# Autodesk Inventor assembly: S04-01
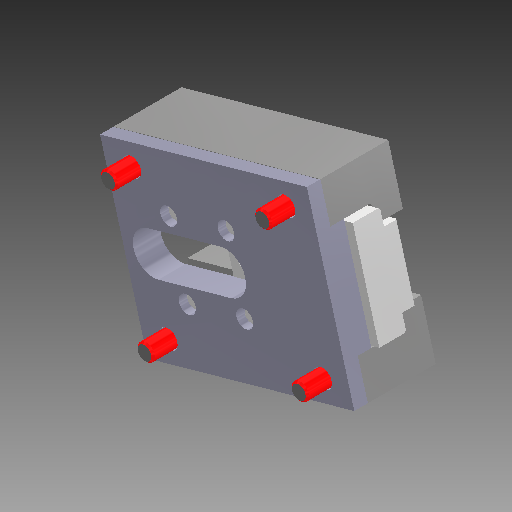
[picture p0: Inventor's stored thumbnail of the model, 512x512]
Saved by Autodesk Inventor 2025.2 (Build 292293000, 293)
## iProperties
Created: 2025-03
Part Number: S04-01
Document SubType Name: Assembly
Designer: Patrik
Stock Number: E 31621_52_30_63
Description: Posuvná jednotka, vsazené vodící lišty
Sending System: KiM GmbH
Major Version: 4.0
Minor Version: 0.0
Format Version: 0.0
Product Id: KiM GmbH
Hersteller: Meusburger
Material: 1.2842
Bestellnummer: E 1265/5
Teilenummer: E 1265/5
Beschreibung: Druckstück gefedert zum Einpressen _ Spring-loaded thrust piece to be pressed in
cc_prop_force_one_body: 1
Author: Patrik
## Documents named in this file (11)
- C:\Users\Patrik\Documents\Skola\Bakalarska prace\Prakticka cast\Meusburger - sestava - posuvna jednotka\E 31621_52_30_63_MIR.iam
- C:\Users\Patrik\Documents\Skola\Bakalarska prace\Prakticka cast\Meusburger - sestava - posuvna jednotka\E 31621_52_30_63_MIR.ipt
- C:\Users\Patrik\Documents\Skola\Bakalarska prace\Prakticka cast\Meusburger - sestava - posuvna jednotka\E 31621_52_30_63_1_MIR.ipt
- C:\Users\Patrik\Documents\Skola\Bakalarska prace\Prakticka cast\Meusburger - sestava - posuvna jednotka\E 31621_52_30_63_2_MIR.ipt
- C:\Users\Patrik\Documents\Skola\Bakalarska prace\Prakticka cast\Meusburger - sestava - posuvna jednotka\E 31621_52_30_63_3_MIR.ipt
- C:\Users\Patrik\Documents\Skola\Bakalarska prace\Prakticka cast\Meusburger - sestava - posuvna jednotka\E 31621_52_30_63_4_MIR.ipt
- C:\Users\Patrik\Documents\Skola\Bakalarska prace\Prakticka cast\Meusburger - sestava - posuvna jednotka\E 31621_52_30_63_5_MIR.ipt
- C:\Users\Patrik\Documents\Skola\Bakalarska prace\Prakticka cast\Meusburger - sestava - posuvna jednotka\E 31621_52_30_63_6_MIR.ipt
- C:\Users\Patrik\Documents\Skola\Bakalarska prace\Prakticka cast\Meusburger - sestava - posuvna jednotka\E 31621_52_30_63_7_MIR.ipt
- C:\Users\Patrik\Documents\Skola\Bakalarska prace\Prakticka cast\Meusburger - sestava - posuvna jednotka\E 31621_52_30_63_8_MIR.ipt
- C:\Users\Patrik\Documents\Skola\Bakalarska prace\Prakticka cast\Meusburger - sestava - posuvna jednotka\E 31621_52_30_63_9_MIR.ipt
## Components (12 placed, 10 different names)
1. E 31621_52_30_63_MIR:1 — Vložit:2, Vložit:1, Vložit:7, Vložit:6, Vložit:8, Vložit:5, Proti sobě:3, Proti sobě:1, Vložit:4, Vložit:3
2. E 31621_52_30_63_1_MIR:1 — Vložit:2
3. E 31621_52_30_63_2_MIR:1 — Vložit:1
4. E 31621_52_30_63_1_MIR:2 — Vložit:4
5. E 31621_52_30_63_2_MIR:2 — Vložit:3
6. E 31621_52_30_63_3_MIR:1 — Vložit:7, Vložit:6, Vložit:10, Vložit:9
7. E 31621_52_30_63_4_MIR:1 — Vložit:8, Vložit:5, Proti sobě:2, Vložit:12, Vložit:11
8. E 31621_52_30_63_5_MIR:1 — Proti sobě:3, Proti sobě:2, Proti sobě:1
9. E 31621_52_30_63_6_MIR:1 — Vložit:12
10. E 31621_52_30_63_7_MIR:1 — Vložit:10
11. E 31621_52_30_63_8_MIR:1 — Vložit:11
12. E 31621_52_30_63_9_MIR:1 — Vložit:9
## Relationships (15: Insert 12, Mate 3)
- Vložit:2 [Insert]: E 31621_52_30_63_MIR:1 ↔ E 31621_52_30_63_1_MIR:1
- Vložit:1 [Insert]: E 31621_52_30_63_MIR:1 ↔ E 31621_52_30_63_2_MIR:1
- Vložit:7 [Insert]: E 31621_52_30_63_MIR:1 ↔ E 31621_52_30_63_3_MIR:1
- Vložit:6 [Insert]: E 31621_52_30_63_MIR:1 ↔ E 31621_52_30_63_3_MIR:1
- Vložit:8 [Insert]: E 31621_52_30_63_MIR:1 ↔ E 31621_52_30_63_4_MIR:1
- Vložit:5 [Insert]: E 31621_52_30_63_MIR:1 ↔ E 31621_52_30_63_4_MIR:1
- Proti sobě:3 [Mate]: E 31621_52_30_63_MIR:1 ↔ E 31621_52_30_63_5_MIR:1
- Proti sobě:2 [Mate]: E 31621_52_30_63_4_MIR:1 ↔ E 31621_52_30_63_5_MIR:1
- Proti sobě:1 [Mate]: E 31621_52_30_63_MIR:1 ↔ E 31621_52_30_63_5_MIR:1
- Vložit:12 [Insert]: E 31621_52_30_63_4_MIR:1 ↔ E 31621_52_30_63_6_MIR:1
- Vložit:10 [Insert]: E 31621_52_30_63_3_MIR:1 ↔ E 31621_52_30_63_7_MIR:1
- Vložit:11 [Insert]: E 31621_52_30_63_4_MIR:1 ↔ E 31621_52_30_63_8_MIR:1
- Vložit:9 [Insert]: E 31621_52_30_63_3_MIR:1 ↔ E 31621_52_30_63_9_MIR:1
- Vložit:4 [Insert]: E 31621_52_30_63_MIR:1 ↔ E 31621_52_30_63_1_MIR:2
- Vložit:3 [Insert]: E 31621_52_30_63_MIR:1 ↔ E 31621_52_30_63_2_MIR:2
